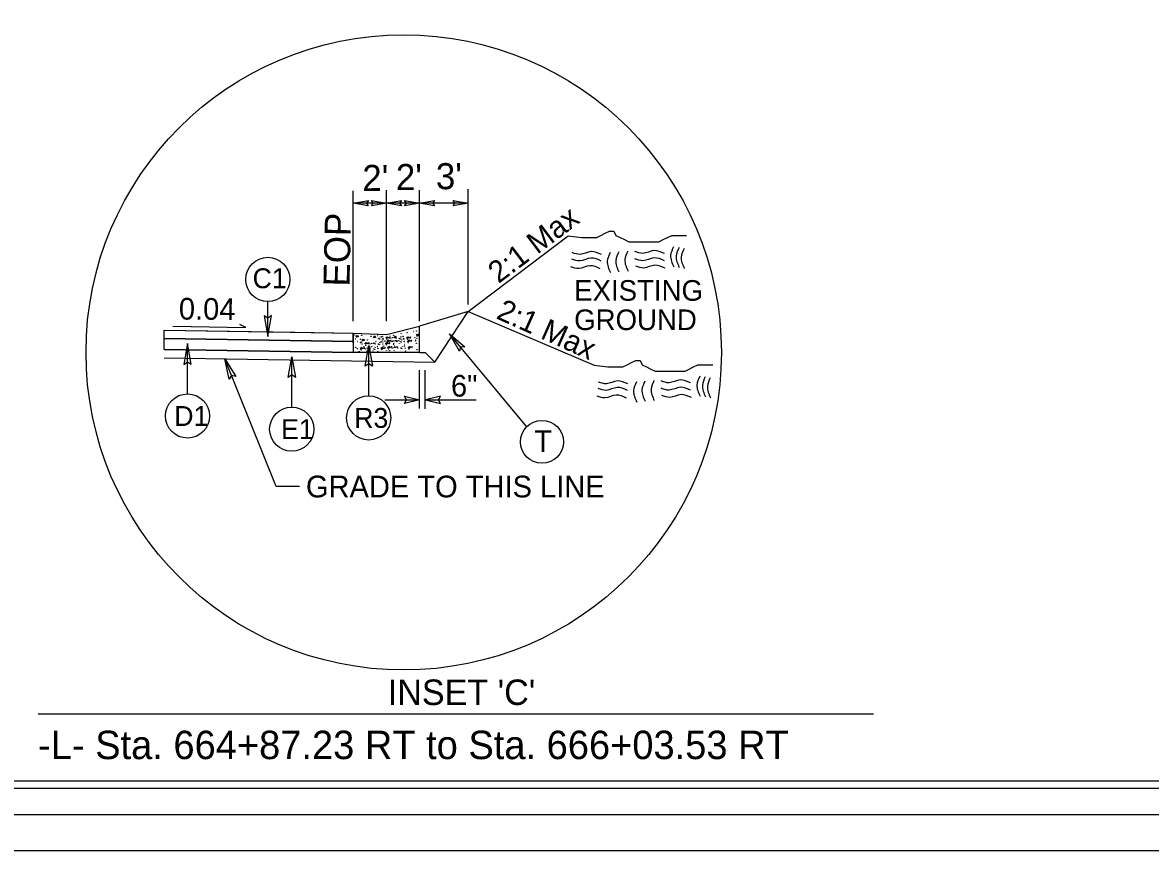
# Model space of a CAD drawing. Extents: x 2294455 to 2294842, y 719496 to 719941.
# Drawn here: x 2294621.8 to 2294702.9, y 719496.2 to 719555.7 of the extents above; entities that cross this region are included whole.
import ezdxf

# ---------------------------------------------------------------- set-up
doc = ezdxf.new("R2010")
doc.units = 0
for name, color, linetype in [('Default', 7, 'Continuous'), ('Old_Level_1', 7, 'Continuous'), ('Old_Level_11', 7, 'Continuous'), ('Old_Level_2', 7, 'Continuous'), ('Old_Level_3', 7, 'Continuous'), ('Prop Dimension Text', 7, 'Continuous'), ('Sheet Cutting Line CELL', 7, 'Continuous'), ('Sheet Plot Border Inside CELL', 7, 'Continuous'), ('Sheet Plot Border Outside CELL', 7, 'Continuous'), ('Sheet Typical CELL', 7, 'Continuous'), ('Typical Curb CELL', 7, 'Continuous'), ('Typical Hinge Slope Arterial CELL', 7, 'Continuous'), ('Typical Hinge Slope Interstate CELL', 7, 'Continuous'), ('Typical ID Circle CELL', 7, 'Continuous'), ('Typical Terminator CELL', 7, 'Continuous'), ('Typical Text ID Circle CELL', 7, 'Continuous')]:
    doc.layers.add(name, color=color, linetype=linetype)

# ---------------------------------------------------------------- blocks, each defined once
blk = doc.blocks.new('TERMINATOR')
at = {"layer": 'Default'}
blk.add_lwpolyline([(-0.357, 0.062), (0, 0), (-0.359, -0.063), (-0.313, 0)], close=True, dxfattribs=at)

msp = doc.modelspace()

# ---------------------------------------------------------------- linework, layer by layer
at = {"layer": 'Default'}
for p, q in [((2294639.468, 719533.145), (2294639.468, 719535.655)), ((2294645.611, 719533.373), (2294645.611, 719533.373)), ((2294633.692, 719529.005), (2294633.692, 719532.626)), ((2294646.716, 719528.866), (2294646.716, 719532.487)), ((2294641.181, 719528.061), (2294641.181, 719531.681)), ((2294640.066, 719522.346), (2294636.37, 719531.538)), ((2294650.375, 719527.968), (2294650.375, 719530.724)), ((2294650.784, 719527.936), (2294650.784, 719530.724)), ((2294647.882, 719528.582), (2294650.375, 719528.582)), ((2294650.784, 719528.582), (2294654.444, 719528.582)), ((2294641.738, 719522.346), (2294640.066, 719522.346))]:
    msp.add_line(p, q, dxfattribs=at)
for points in [[(2294646.687, 719542.538), (2294645.611, 719542.718), (2294646.692, 719542.914), (2294646.555, 719542.723)], [(2294646.919, 719542.908), (2294647.993, 719542.718), (2294646.911, 719542.532), (2294647.05, 719542.723)], [(2294649.069, 719542.538), (2294647.993, 719542.718), (2294649.074, 719542.914), (2294648.937, 719542.723)], [(2294649.301, 719542.908), (2294650.375, 719542.718), (2294649.293, 719542.532), (2294649.432, 719542.723)], [(2294651.452, 719542.538), (2294650.375, 719542.718), (2294651.456, 719542.914), (2294651.319, 719542.723)], [(2294652.787, 719542.908), (2294653.862, 719542.718), (2294652.78, 719542.532), (2294652.918, 719542.723)], [(2294639.211, 719534.633), (2294639.468, 719533.145), (2294639.732, 719534.641), (2294639.468, 719534.451)], [(2294633.948, 719531.138), (2294633.692, 719532.626), (2294633.427, 719531.13), (2294633.692, 719531.32)], [(2294646.46, 719530.999), (2294646.716, 719532.487), (2294646.981, 719530.99), (2294646.716, 719531.181)], [(2294640.925, 719530.193), (2294641.181, 719531.681), (2294641.446, 719530.185), (2294641.181, 719530.375)], [(2294636.689, 719530.064), (2294636.372, 719531.54), (2294637.175, 719530.25), (2294636.859, 719530.328)]]:
    msp.add_lwpolyline(points, close=True, dxfattribs=at)
for points in [[(2294632.021, 719532.998), (2294632.021, 719532.998), (2294632.021, 719533.593), (2294645.611, 719533.373)], [(2294645.611, 719533.373), (2294645.611, 719533.373), (2294645.611, 719532.778)], [(2294645.611, 719532.778), (2294632.021, 719532.998)]]:
    msp.add_lwpolyline(points, dxfattribs=at)
for centre in [(2294639.468, 719537.242), (2294633.692, 719527.418), (2294646.716, 719527.278), (2294641.181, 719526.473)]:
    msp.add_circle(centre, 1.588, dxfattribs=at)
at = {"layer": 'Old_Level_1'}
for p, q in [((2294647.993, 719534.237), (2294647.993, 719543.671)), ((2294650.375, 719534.237), (2294650.375, 719543.671)), ((2294653.862, 719535.429), (2294653.862, 719543.726)), ((2294653.862, 719534.943), (2294650.375, 719533.869)), ((2294651.481, 719531.286), (2294653.862, 719534.943)), ((2294632.021, 719533.593), (2294641.398, 719533.442)), ((2294632.625, 719533.874), (2294637.88, 719533.789)), ((2294637.88, 719533.789), (2294637.462, 719533.996)), ((2294641.398, 719533.442), (2294645.611, 719533.373)), ((2294632.016, 719532.204), (2294632.021, 719532.998)), ((2294632.021, 719532.998), (2294645.611, 719532.778)), ((2294632.021, 719532.998), (2294645.611, 719532.778)), ((2294645.611, 719532.778), (2294645.606, 719531.984)), ((2294632.006, 719531.608), (2294651.481, 719531.286)), ((2294632.016, 719532.204), (2294645.606, 719531.984)), ((2294645.606, 719531.984), (2294632.016, 719532.204)), ((2294632.016, 719532.204), (2294632.016, 719532.204)), ((2294650.375, 719531.984), (2294650.784, 719531.984))]:
    msp.add_line(p, q, dxfattribs=at)
msp.add_lwpolyline([(2294651.481, 719531.286), (2294650.784, 719531.984)], dxfattribs=at)
at = {"layer": 'Old_Level_11'}
for p, q in [((2294645.611, 719534.237), (2294645.611, 719543.615)), ((2294647.993, 719542.718), (2294645.611, 719542.718)), ((2294650.375, 719542.718), (2294647.993, 719542.718)), ((2294653.862, 719542.718), (2294650.375, 719542.718)), ((2294622.947, 719505.99), (2294683.028, 719505.99))]:
    msp.add_line(p, q, dxfattribs=at)
msp.add_circle((2294649.235, 719531.994), 22.845, dxfattribs=at)
at = {"layer": 'Old_Level_2'}
for points in [[(2294663.466, 719539.029), (2294662.712, 719539.243), (2294661.921, 719539.04), (2294661.346, 719539.167)], [(2294663.466, 719539.029), (2294662.712, 719539.243), (2294661.921, 719539.04), (2294661.346, 719539.167)], [(2294664.088, 719539.172), (2294663.876, 719538.55), (2294664.105, 719537.728)], [(2294664.088, 719539.172), (2294663.876, 719538.55), (2294664.105, 719537.728)], [(2294664.694, 719539.226), (2294664.483, 719538.604), (2294664.709, 719537.78)], [(2294664.694, 719539.226), (2294664.483, 719538.604), (2294664.709, 719537.78)], [(2294665.35, 719539.277), (2294665.141, 719538.657), (2294665.365, 719537.833)], [(2294665.35, 719539.277), (2294665.141, 719538.657), (2294665.365, 719537.833)], [(2294667.979, 719539.099), (2294667.23, 719539.316), (2294666.431, 719539.113), (2294665.861, 719539.242)], [(2294667.979, 719539.099), (2294667.23, 719539.316), (2294666.431, 719539.113), (2294665.861, 719539.242)], [(2294668.644, 719539.584), (2294668.43, 719538.962), (2294668.659, 719538.14)], [(2294668.644, 719539.584), (2294668.43, 719538.962), (2294668.659, 719538.14)], [(2294669.032, 719539.543), (2294668.823, 719538.921), (2294669.052, 719538.097)], [(2294669.032, 719539.543), (2294668.823, 719538.921), (2294669.052, 719538.097)], [(2294669.397, 719539.472), (2294669.186, 719538.852), (2294669.414, 719538.028)], [(2294669.397, 719539.472), (2294669.186, 719538.852), (2294669.414, 719538.028)], [(2294663.369, 719538.011), (2294662.618, 719538.226), (2294661.822, 719538.023), (2294661.25, 719538.152)], [(2294663.369, 719538.011), (2294662.618, 719538.226), (2294661.822, 719538.023), (2294661.25, 719538.152)], [(2294663.446, 719538.557), (2294662.692, 719538.773), (2294661.901, 719538.568), (2294661.326, 719538.697)], [(2294663.446, 719538.557), (2294662.692, 719538.773), (2294661.901, 719538.568), (2294661.326, 719538.697)], [(2294667.983, 719538.577), (2294667.23, 719538.789), (2294666.438, 719538.586), (2294665.866, 719538.716)], [(2294667.983, 719538.577), (2294667.23, 719538.789), (2294666.438, 719538.586), (2294665.866, 719538.716)], [(2294668.042, 719538.048), (2294667.29, 719538.26), (2294666.492, 719538.062), (2294665.92, 719538.189)], [(2294668.042, 719538.048), (2294667.29, 719538.26), (2294666.492, 719538.062), (2294665.92, 719538.189)], [(2294669.865, 719529.794), (2294669.116, 719530.011), (2294668.318, 719529.808), (2294667.748, 719529.937)], [(2294669.865, 719529.794), (2294669.116, 719530.011), (2294668.318, 719529.808), (2294667.748, 719529.937)], [(2294670.53, 719530.279), (2294670.317, 719529.657), (2294670.545, 719528.835)], [(2294670.53, 719530.279), (2294670.317, 719529.657), (2294670.545, 719528.835)], [(2294670.919, 719530.238), (2294670.71, 719529.616), (2294670.938, 719528.792)], [(2294670.919, 719530.238), (2294670.71, 719529.616), (2294670.938, 719528.792)], [(2294671.284, 719530.167), (2294671.073, 719529.547), (2294671.301, 719528.723)], [(2294671.284, 719530.167), (2294671.073, 719529.547), (2294671.301, 719528.723)], [(2294665.333, 719529.251), (2294664.579, 719529.468), (2294663.787, 719529.263), (2294663.213, 719529.392)], [(2294665.333, 719529.251), (2294664.579, 719529.468), (2294663.787, 719529.263), (2294663.213, 719529.392)], [(2294665.352, 719529.723), (2294664.599, 719529.938), (2294663.807, 719529.735), (2294663.233, 719529.862)], [(2294665.352, 719529.723), (2294664.599, 719529.938), (2294663.807, 719529.735), (2294663.233, 719529.862)], [(2294665.974, 719529.867), (2294665.763, 719529.245), (2294665.991, 719528.423)], [(2294665.974, 719529.867), (2294665.763, 719529.245), (2294665.991, 719528.423)], [(2294666.581, 719529.921), (2294666.369, 719529.299), (2294666.596, 719528.475)], [(2294666.581, 719529.921), (2294666.369, 719529.299), (2294666.596, 719528.475)], [(2294667.237, 719529.972), (2294667.028, 719529.352), (2294667.251, 719528.528)], [(2294667.237, 719529.972), (2294667.028, 719529.352), (2294667.251, 719528.528)], [(2294669.87, 719529.272), (2294669.116, 719529.484), (2294668.325, 719529.281), (2294667.753, 719529.41)], [(2294669.87, 719529.272), (2294669.116, 719529.484), (2294668.325, 719529.281), (2294667.753, 719529.41)], [(2294665.256, 719528.706), (2294664.505, 719528.92), (2294663.709, 719528.718), (2294663.136, 719528.847)], [(2294665.256, 719528.706), (2294664.505, 719528.92), (2294663.709, 719528.718), (2294663.136, 719528.847)], [(2294669.928, 719528.743), (2294669.176, 719528.955), (2294668.378, 719528.757), (2294667.806, 719528.884)], [(2294669.928, 719528.743), (2294669.176, 719528.955), (2294668.378, 719528.757), (2294667.806, 719528.884)]]:
    msp.add_spline(points, degree=3, dxfattribs=at)
at = {"layer": 'Sheet Cutting Line CELL'}
msp.add_line((2294454.524, 719496.169), (2294791.324, 719496.169), dxfattribs=at)
at = {"layer": 'Sheet Plot Border Inside CELL'}
msp.add_lwpolyline([(2294790.424, 719711.679), (2294457.124, 719711.679), (2294457.124, 719500.659), (2294790.424, 719500.659)], close=True, dxfattribs=at)
at = {"layer": 'Sheet Plot Border Outside CELL'}
for points in [[(2294793.79, 719718.758), (2294456.99, 719718.758), (2294456.99, 719498.758), (2294793.79, 719498.758)], [(2294791.324, 719716.169), (2294454.524, 719716.169), (2294454.524, 719496.169), (2294791.324, 719496.169)]]:
    msp.add_lwpolyline(points, close=True, dxfattribs=at)
at = {"layer": 'Sheet Typical CELL'}
msp.add_lwpolyline([(2294787.924, 719711.169), (2294487.924, 719711.169), (2294487.924, 719501.169), (2294787.924, 719501.169)], close=True, dxfattribs=at)
at = {"layer": 'Typical Curb CELL'}
for p, q in [((2294645.611, 719532.678), (2294645.611, 719533.373)), ((2294645.611, 719533.373), (2294647.993, 719533.274)), ((2294645.813, 719533.097), (2294645.916, 719533.24)), ((2294645.916, 719533.24), (2294645.957, 719533.105)), ((2294647.993, 719533.274), (2294650.375, 719533.869)), ((2294650.148, 719533.274), (2294650.168, 719533.166)), ((2294650.332, 719533.22), (2294650.148, 719533.274)), ((2294650.168, 719533.166), (2294650.332, 719533.22)), ((2294650.375, 719531.984), (2294650.375, 719533.869)), ((2294645.957, 719533.105), (2294645.813, 719533.097)), ((2294646.24, 719532.814), (2294646.315, 719532.95)), ((2294646.438, 719532.861), (2294646.24, 719532.814)), ((2294646.315, 719532.95), (2294646.438, 719532.861)), ((2294646.464, 719532.578), (2294646.538, 719532.715)), ((2294646.661, 719532.626), (2294646.464, 719532.578)), ((2294646.538, 719532.715), (2294646.661, 719532.626)), ((2294647.183, 719532.647), (2294647.041, 719532.639)), ((2294647.06, 719533.045), (2294647.163, 719533.188)), ((2294647.204, 719533.053), (2294647.06, 719533.045)), ((2294647.163, 719533.188), (2294647.204, 719533.053)), ((2294647.951, 719532.578), (2294648.026, 719532.715)), ((2294648.149, 719532.626), (2294647.951, 719532.578)), ((2294647.972, 719532.984), (2294648.047, 719533.121)), ((2294648.17, 719533.032), (2294647.972, 719532.984)), ((2294648.026, 719532.715), (2294648.149, 719532.626)), ((2294648.037, 719532.755), (2294648.111, 719532.891)), ((2294648.234, 719532.802), (2294648.037, 719532.755)), ((2294648.047, 719533.121), (2294648.17, 719533.032)), ((2294648.087, 719532.297), (2294648.161, 719532.434)), ((2294648.111, 719532.891), (2294648.234, 719532.802)), ((2294648.161, 719532.434), (2294648.284, 719532.345)), ((2294648.549, 719533.045), (2294648.651, 719533.188)), ((2294648.692, 719533.053), (2294648.549, 719533.045)), ((2294648.756, 719532.823), (2294648.613, 719532.815)), ((2294648.651, 719533.188), (2294648.692, 719533.053)), ((2294649.46, 719532.984), (2294649.534, 719533.121)), ((2294649.657, 719533.032), (2294649.46, 719532.984)), ((2294649.524, 719532.755), (2294649.599, 719532.891)), ((2294649.721, 719532.802), (2294649.524, 719532.755)), ((2294649.534, 719533.121), (2294649.657, 719533.032)), ((2294649.574, 719532.297), (2294649.649, 719532.434)), ((2294649.599, 719532.891), (2294649.721, 719532.802)), ((2294649.649, 719532.434), (2294649.772, 719532.345)), ((2294650.375, 719531.984), (2294645.606, 719531.984)), ((2294646.12, 719532.235), (2294646.195, 719532.371)), ((2294646.318, 719532.282), (2294646.12, 719532.235)), ((2294646.195, 719532.371), (2294646.318, 719532.282)), ((2294646.84, 719532.303), (2294646.697, 719532.296)), ((2294647.608, 719532.235), (2294647.682, 719532.371)), ((2294647.805, 719532.282), (2294647.608, 719532.235)), ((2294647.682, 719532.371), (2294647.805, 719532.282)), ((2294648.284, 719532.345), (2294648.087, 719532.297)), ((2294648.806, 719532.366), (2294648.664, 719532.358)), ((2294649.772, 719532.345), (2294649.574, 719532.297))]:
    msp.add_line(p, q, dxfattribs=at)
for centre in [(2294645.73, 719533.252), (2294646.21, 719533.217), (2294646.93, 719533.298), (2294648.508, 719533.228), (2294649.051, 719533.332), (2294649.479, 719533.408), (2294649.929, 719533.494), (2294650.166, 719533.523), (2294650.298, 719533.322), (2294645.777, 719532.968), (2294645.915, 719532.778), (2294646.123, 719532.939), (2294646.125, 719532.699), (2294646.185, 719532.735), (2294646.241, 719532.597), (2294646.376, 719532.412), (2294646.464, 719533.205), (2294646.472, 719532.644), (2294646.515, 719532.505), (2294646.643, 719532.876), (2294646.717, 719532.625), (2294646.737, 719532.685), (2294646.817, 719532.585), (2294646.885, 719533.149), (2294646.925, 719532.401), (2294646.932, 719532.64), (2294647.043, 719532.651), (2294647.186, 719532.591), (2294647.232, 719532.789), (2294647.358, 719532.435), (2294647.367, 719533.209), (2294647.417, 719532.591), (2294647.438, 719532.997), (2294647.484, 719532.55), (2294647.505, 719532.956), (2294647.523, 719532.701), (2294647.544, 719533.107), (2294647.607, 719532.772), (2294647.634, 719533.105), (2294647.673, 719532.735), (2294647.694, 719533.141), (2294647.698, 719532.875), (2294647.729, 719532.597), (2294647.748, 719532.418), (2294647.749, 719533.003), (2294647.758, 719532.911), (2294647.808, 719532.454), (2294647.814, 719532.774), (2294647.885, 719532.818), (2294647.949, 719532.588), (2294647.96, 719532.644), (2294647.981, 719533.05), (2294647.994, 719532.523), (2294648.023, 719532.911), (2294648.045, 719532.82), (2294648.087, 719532.681), (2294648.205, 719532.625), (2294648.226, 719533.031), (2294648.225, 719532.685), (2294648.246, 719533.091), (2294648.258, 719533.161), (2294648.29, 719532.801), (2294648.31, 719532.861), (2294648.326, 719532.991), (2294648.36, 719532.404), (2294648.39, 719532.762), (2294648.433, 719532.807), (2294648.44, 719533.046), (2294648.498, 719532.577), (2294648.505, 719532.816), (2294648.531, 719532.651), (2294648.552, 719533.057), (2294648.565, 719532.464), (2294648.616, 719532.827), (2294648.695, 719532.997), (2294648.759, 719532.767), (2294648.867, 719532.841), (2294648.926, 719532.997), (2294648.931, 719532.611), (2294648.99, 719532.767), (2294648.993, 719532.956), (2294649.032, 719533.107), (2294649.057, 719532.726), (2294649.096, 719532.877), (2294649.146, 719532.42), (2294649.182, 719533.141), (2294649.237, 719533.003), (2294649.242, 719532.789), (2294649.246, 719532.911), (2294649.296, 719532.454), (2294649.302, 719532.774), (2294649.306, 719532.559), (2294649.469, 719533.05), (2294649.503, 719532.929), (2294649.533, 719532.82), (2294649.567, 719532.699), (2294649.713, 719533.031), (2294649.734, 719533.091), (2294649.778, 719532.801), (2294649.798, 719532.861), (2294649.848, 719532.404), (2294650.04, 719533.057), (2294650.074, 719532.87), (2294650.104, 719532.827), (2294650.138, 719532.64), (2294650.183, 719532.997), (2294645.782, 719532.355), (2294645.842, 719532.391), (2294645.898, 719532.254), (2294646.033, 719532.069), (2294646.129, 719532.301), (2294646.171, 719532.161), (2294646.374, 719532.281), (2294646.394, 719532.341), (2294646.474, 719532.242), (2294646.581, 719532.057), (2294646.588, 719532.296), (2294646.7, 719532.307), (2294646.843, 719532.247), (2294647.015, 719532.092), (2294647.074, 719532.247), (2294647.141, 719532.207), (2294647.18, 719532.357), (2294647.33, 719532.391), (2294647.386, 719532.254), (2294647.39, 719532.04), (2294647.617, 719532.301), (2294647.651, 719532.179), (2294647.733, 719532.383), (2294647.862, 719532.281), (2294647.864, 719532.316), (2294647.882, 719532.341), (2294647.999, 719532.131), (2294648.095, 719532.363), (2294648.138, 719532.224), (2294648.188, 719532.307), (2294648.222, 719532.121), (2294648.34, 719532.344), (2294648.44, 719532.304), (2294648.548, 719532.119), (2294648.555, 719532.359), (2294648.666, 719532.37), (2294648.809, 719532.31), (2294648.981, 719532.154), (2294649.04, 719532.31), (2294649.107, 719532.269), (2294649.352, 719532.316), (2294649.356, 719532.102), (2294649.583, 719532.363), (2294649.617, 719532.242), (2294649.828, 719532.344), (2294650.154, 719532.37), (2294650.188, 719532.183)]:
    msp.add_circle(centre, 0.00955, dxfattribs=at)
at = {"layer": 'Typical Hinge Slope Arterial CELL'}
for points in [[(2294661.05, 719540.379), (2294662.035, 719540.257), (2294662.343, 719540.257), (2294662.806, 719540.257), (2294663.114, 719540.257), (2294663.422, 719540.41), (2294663.73, 719540.565), (2294664.038, 719540.719), (2294664.346, 719540.719), (2294664.5, 719540.41), (2294664.808, 719540.257), (2294665.116, 719540.102), (2294665.424, 719539.949), (2294665.732, 719539.949), (2294666.04, 719539.949), (2294666.348, 719539.949), (2294666.656, 719539.949), (2294666.964, 719539.949), (2294667.272, 719539.949), (2294667.58, 719539.949), (2294667.888, 719540.102), (2294668.196, 719540.257), (2294668.504, 719540.41), (2294668.966, 719540.41), (2294669.274, 719540.41), (2294669.582, 719540.41)], [(2294662.937, 719531.074), (2294663.922, 719530.952), (2294664.23, 719530.952), (2294664.693, 719530.952), (2294665, 719530.952), (2294665.308, 719531.105), (2294665.616, 719531.26), (2294665.924, 719531.414), (2294666.232, 719531.414), (2294666.387, 719531.105), (2294666.695, 719530.952), (2294667.003, 719530.797), (2294667.311, 719530.644), (2294667.619, 719530.644), (2294667.927, 719530.644), (2294668.235, 719530.644), (2294668.543, 719530.644), (2294668.851, 719530.644), (2294669.159, 719530.644), (2294669.467, 719530.644), (2294669.774, 719530.797), (2294670.082, 719530.952), (2294670.39, 719531.105), (2294670.853, 719531.105), (2294671.161, 719531.105), (2294671.469, 719531.105)]]:
    msp.add_lwpolyline(points, dxfattribs=at)
at = {"layer": 'Typical Hinge Slope Interstate CELL'}
for q in [(2294661.05, 719540.379), (2294662.94, 719531.081)]:
    msp.add_line((2294653.862, 719534.943), q, dxfattribs=at)
at = {"layer": 'Typical ID Circle CELL'}
msp.add_line((2294658.087, 719526.65), (2294652.52, 719533.328), dxfattribs=at)
msp.add_circle((2294659.179, 719525.558), 1.545, dxfattribs=at)
at = {"layer": 'Typical Terminator CELL'}
msp.add_lwpolyline([(2294653.247, 719532.072), (2294652.52, 719533.328), (2294653.636, 719532.386), (2294653.324, 719532.364)], close=True, dxfattribs=at)

# ---------------------------------------------------------------- block references
at = {"layer": 'Default', "xscale": 3.0310846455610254}
for p, yscale, rotation in [((2294650.375, 719528.582), 4.350552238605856, 5.19885055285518e-05), ((2294650.793, 719528.584), -4.350552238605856, -179.99994800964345)]:
    msp.add_blockref('TERMINATOR', p, dxfattribs=dict(at, yscale=yscale, rotation=rotation))

# ---------------------------------------------------------------- texts
at = {"layer": 'Default'}
for s, p in [('C1', (2294638.372, 719536.61)), ('D1', (2294632.74, 719526.703)), ('R3', (2294645.681, 719526.564)), ('E1', (2294640.423, 719525.758))]:
    msp.add_text(s, height=1.4292, rotation=0.00005, dxfattribs=at).set_placement(p)
at = {"layer": 'Old_Level_1'}
for s, height, rotation, p in [('EXISTING', 1.4844, 359.99996, (2294661.492, 719535.706)), ('0.04', 1.5625, 359.52813, (2294633.063, 719534.354)), ('GROUND', 1.4844, 359.99996, (2294661.492, 719533.596)), ("INSET 'C'", 1.8334, 359.99996, (2294648.09, 719506.631)), ('-L- Sta. 664+87.23 RT to Sta. 666+03.53 RT', 2.04545, 0, (2294622.947, 719502.738))]:
    msp.add_text(s, height=height, rotation=rotation, dxfattribs=at).set_placement(p)
at = {"layer": 'Old_Level_11'}
msp.add_text('GRADE TO THIS LINE', height=1.5625, rotation=359.99996, dxfattribs=at).set_placement((2294642.205, 719521.563))
at = {"layer": 'Old_Level_3'}
for s, rotation, p in [("2'", 0.16712, (2294646.261, 719543.599)), ("2'", 0.16712, (2294648.674, 719543.664)), ("3'", 0.16712, (2294651.55, 719543.727)), ('EOP', 88.71174, (2294645.335, 719536.716))]:
    msp.add_text(s, height=1.875, rotation=rotation, dxfattribs=at).set_placement(p)
at = {"layer": 'Prop Dimension Text'}
msp.add_text('6"', height=1.5625, dxfattribs=at).set_placement((2294652.634, 719528.812))
at = {"layer": 'Typical Hinge Slope Interstate CELL'}
for rotation, p in [(36.99104, (2294656.056, 719536.908)), (335.8788, (2294655.813, 719534.461))]:
    msp.add_text('2:1 Max', height=1.5625, rotation=rotation, dxfattribs=at).set_placement(p)
at = {"layer": 'Typical Text ID Circle CELL'}
msp.add_text('T', height=1.562, dxfattribs=at).set_placement((2294658.62, 719524.819))

doc.saveas('drawing.dxf')
